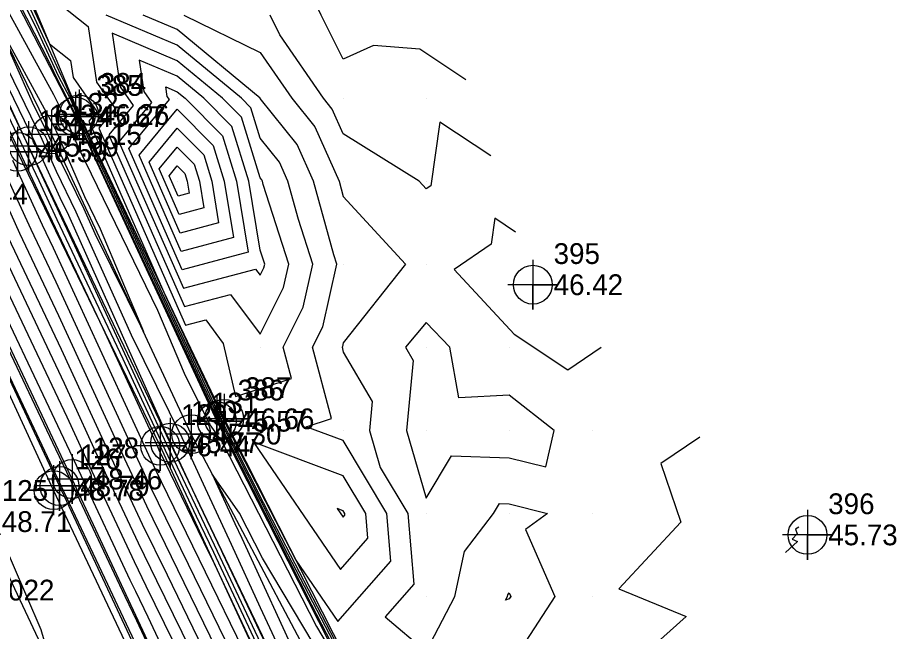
# Model space of a CAD drawing. Extents: x 2090860 to 2091277, y 159470 to 160080.
# Drawn here: x 2091170.8 to 2091276.6, y 159525.8 to 159599.7 of the extents above; entities that cross this region are included whole.
import ezdxf

# ---------------------------------------------------------------- set-up
doc = ezdxf.new("R2010")
doc.units = 0
for name, color, linetype in [('DTM Contours Major', 7, 'Continuous'), ('DTM Contours Minor', 7, 'Continuous'), ('Exist DTM Breakline', 7, 'Continuous'), ('Exist DTM Breakline Cogo Elevation', 7, 'Continuous'), ('Exist DTM Breakline Cogo Number', 7, 'Continuous'), ('Exist DTM Breakline Cogo Point CELL', 7, 'Continuous'), ('Exist DTM Crownline', 7, 'Continuous'), ('Exist DTM QL2 LIDAR Elevation Point', 7, 'Continuous'), ('Exist DTM Regular Point CELL', 7, 'Continuous'), ('Exist DTM Regular Point Cogo Elevation', 7, 'Continuous'), ('Exist DTM Regular Point Cogo Number', 7, 'Continuous'), ('Exist Roads EOP', 7, 'Continuous'), ('Exist Roads EOP Cogo Elevation', 7, 'Continuous'), ('Exist Roads EOP Cogo Number', 7, 'Continuous'), ('Exist Roads EOP Cogo Point CELL', 7, 'Continuous'), ('Exist Roads EOT', 7, 'Continuous'), ('Exist Roads EOT Cogo Comment', 7, 'Continuous'), ('Exist Roads EOT Cogo Elevation', 7, 'Continuous'), ('Exist Roads EOT Cogo Number', 7, 'Continuous'), ('Exist Roads EOT Cogo Point CELL', 7, 'Continuous')]:
    doc.layers.add(name, color=color, linetype=linetype)

msp = doc.modelspace()

# ---------------------------------------------------------------- linework, layer by layer
at = {"layer": 'DTM Contours Major'}
for points in [[(2091162.22, 159619.59), (2091172.87, 159598.82), (2091175.68, 159592.7), (2091177.05, 159590.04), (2091177.99, 159587.93), (2091182.7, 159577.85), (2091190.68, 159560.74), (2091193.18, 159555.38), (2091195.13, 159551.22), (2091203.3, 159535.13), (2091208.82, 159524.5), (2091210.51, 159521.16), (2091212.36, 159517.6), (2091212.6, 159516.12), (2091218.27, 159517.95), (2091225.53, 159506.04)], [(2091207.68, 159508.27), (2091198.7, 159527.23), (2091194.86, 159535.4), (2091190.69, 159544.21), (2091188.73, 159548.38), (2091177.66, 159572.24), (2091176.09, 159575.54), (2091172.14, 159584.12), (2091172.1, 159584.21), (2091171.96, 159584.5), (2091159.16, 159611.27)], [(2091227.76, 159583.05), (2091221.65, 159587.11), (2091220.56, 159579.46), (2091220, 159579.08), (2091219.16, 159580), (2091210, 159585.73), (2091208.68, 159588.68), (2091207.63, 159590), (2091202.35, 159597.65), (2091201.18, 159600)], [(2091200.18, 159580.18), (2091200, 159580.41), (2091197.73, 159587.73), (2091195.47, 159590), (2091190, 159594.52), (2091182.17, 159597.83), (2091183.14, 159591.36), (2091184.7, 159589.12), (2091181.77, 159585.59), (2091190.87, 159564.9), (2091196.43, 159566.38), (2091200, 159561.59), (2091202.8, 159567.2), (2091203.44, 159570), (2091200.37, 159579.63), (2091200.26, 159580), (2091200.18, 159580.18)], [(2091186.61, 159582.31), (2091190, 159586.4), (2091193.19, 159583.19), (2091194.18, 159580), (2091194.99, 159575.01), (2091190.36, 159573.77), (2091186.61, 159582.31)], [(2091204.41, 159506.84), (2091201.72, 159512.58), (2091191.37, 159533.84), (2091186.84, 159543.13), (2091185.01, 159547.03), (2091175.43, 159567.86), (2091172.41, 159574.21), (2091169.37, 159580.83)], [(2091199.12, 159504.14), (2091189.54, 159524.53), (2091186.27, 159531.24), (2091184.84, 159534.18), (2091179.74, 159545.05), (2091176.73, 159551.58), (2091166.95, 159572.18)], [(2091235.41, 159550), (2091230, 159554.23), (2091223.93, 159553.93), (2091222.82, 159560), (2091220, 159562.98), (2091217.49, 159560), (2091218.42, 159558.42), (2091217.63, 159550), (2091220, 159541.83), (2091223.05, 159546.95), (2091230, 159546.68), (2091234.41, 159545.59), (2091235.41, 159550)], [(2091252.96, 159549.2), (2091248.25, 159545.99), (2091250.64, 159538.93), (2091243.2, 159530.91), (2091251.29, 159527.59), (2091233.2, 159511.35)], [(2091210.19, 159540), (2091210, 159540.31), (2091209.25, 159540.59), (2091209.98, 159539.53), (2091210.21, 159539.79), (2091210.19, 159540)]]:
    msp.add_lwpolyline(points, dxfattribs=at)
at = {"layer": 'DTM Contours Minor'}
for points in [[(2091224.76, 159592.22), (2091219.22, 159595.9), (2091213.64, 159596.36), (2091210, 159594.69), (2091207.35, 159600), (2091204.79, 159605.21), (2091210, 159605.72), (2091210.64, 159610.83), (2091203.95, 159619.56), (2091203.03, 159627.79), (2091199.27, 159639.53), (2091192.99, 159662.41), (2091180.9, 159659.1), (2091180, 159656.91), (2091179.57, 159659.57), (2091178.38, 159660), (2091170, 159666.16)], [(2091219.63, 159519.56), (2091212.69, 159517.33), (2091212.63, 159517.73), (2091209.73, 159523.3), (2091209.08, 159524.59), (2091200.41, 159541.27), (2091195.33, 159551.28), (2091192.24, 159557.89), (2091190.87, 159560.84), (2091186.47, 159570.26), (2091178.17, 159588.03), (2091176.51, 159591.76), (2091176.02, 159592.72), (2091171.12, 159603.39), (2091162.73, 159619.75)], [(2091161.72, 159619.42), (2091174.62, 159594.26), (2091175.34, 159592.69), (2091177.59, 159588.32), (2091177.81, 159587.82), (2091178.92, 159585.45), (2091190.5, 159560.64), (2091194.12, 159552.87), (2091194.92, 159551.15), (2091206.18, 159528.99), (2091208.56, 159524.42), (2091211.29, 159519.03), (2091212.1, 159517.48), (2091212.51, 159514.92), (2091216.91, 159516.34), (2091222.54, 159507.09)], [(2091206.7, 159507.96), (2091205.1, 159511.33), (2091194.5, 159533.92), (2091193.91, 159535.13), (2091187.84, 159547.61), (2091187.65, 159548.02), (2091181.1, 159562.25), (2091174.97, 159575.16), (2091174.59, 159575.99), (2091170.96, 159583.65), (2091159.14, 159608.41)], [(2091208.17, 159508.43), (2091195.49, 159535.18), (2091195.33, 159535.53), (2091192.74, 159540.99), (2091189.37, 159548.23), (2091189.23, 159548.54), (2091188.88, 159549.24), (2091176.93, 159575.88), (2091175.9, 159577.99), (2091172.91, 159584.62), (2091161.2, 159608.69)], [(2091169.37, 159607.95), (2091174.6, 159596.57), (2091177.15, 159594.53), (2091177.46, 159592.48), (2091180.32, 159588.39), (2091179.36, 159587.24), (2091188.68, 159566.02), (2091190.25, 159562.66), (2091191.05, 159560.94), (2091191.3, 159560.4), (2091195.53, 159551.35), (2091197.53, 159547.41), (2091204.3, 159534.37), (2091209.35, 159526.97), (2091215.74, 159534.26), (2091215.24, 159540), (2091210, 159548.77), (2091205.55, 159550.43), (2091208.59, 159551.41), (2091206.3, 159560), (2091207.53, 159562.47), (2091209.23, 159570), (2091208.87, 159571.13), (2091206.41, 159580), (2091204.43, 159584.43), (2091200, 159589.98), (2091200, 159590), (2091199.99, 159590), (2091190, 159598.26), (2091185.89, 159600)], [(2091170.93, 159605.31), (2091179.29, 159598.64), (2091180.3, 159591.92), (2091182.51, 159588.76), (2091180.57, 159586.41), (2091190.99, 159562.68), (2091193.43, 159563.33), (2091195.55, 159560.48), (2091197.01, 159554.08), (2091203.75, 159556.25), (2091202.75, 159560), (2091205.17, 159564.83), (2091206.33, 159570), (2091204.62, 159575.38), (2091203.34, 159580), (2091202.31, 159582.31), (2091200, 159585.2), (2091198.86, 159588.86), (2091197.73, 159590), (2091190, 159596.39), (2091181.46, 159600)], [(2091168.28, 159602.91), (2091175.11, 159590.44), (2091176.8, 159587.07), (2091178.21, 159583.85), (2091187.64, 159564.48), (2091190.82, 159556.88), (2091193.94, 159550.68), (2091195.4, 159548.57), (2091206.77, 159526.37), (2091208.71, 159523.12), (2091211.92, 159516.82), (2091212.41, 159513.72), (2091215.54, 159514.73), (2091219.56, 159508.15)], [(2091190.81, 159600), (2091200, 159595.52), (2091203.81, 159590), (2091206.56, 159586.56), (2091209.49, 159580), (2091210, 159578.15), (2091217.5, 159570), (2091210, 159560.55), (2091209.9, 159560.1), (2091209.85, 159560), (2091210, 159559.43), (2091213.49, 159553.49), (2091213.16, 159550), (2091214.46, 159545.54), (2091217.77, 159540), (2091218.51, 159531.49), (2091215.05, 159527.53), (2091220, 159523.35), (2091223.42, 159530), (2091224.6, 159535.4), (2091228.1, 159540), (2091228.81, 159541.19), (2091230, 159541.14), (2091234.61, 159540), (2091231.96, 159538.04), (2091235.5, 159530), (2091230, 159521.53)], [(2091209.19, 159508.99), (2091200.05, 159528.61), (2091196.54, 159536.26), (2091193.16, 159543.51), (2091190.6, 159549.1), (2091184.5, 159561.46), (2091177.85, 159576.26), (2091175.47, 159581.17), (2091173.72, 159585.04), (2091166.89, 159599.08)], [(2091168.13, 159599.43), (2091174.94, 159587), (2091175.42, 159586.04), (2091178.85, 159578.16), (2091180.74, 159574.28), (2091185.93, 159561.89), (2091180.11, 159573.68), (2091178.78, 159576.64), (2091175.04, 159584.35), (2091174.54, 159585.46), (2091172.59, 159589.47), (2091168.13, 159599.43)], [(2091207.19, 159508.12), (2091201.9, 159519.28), (2091194.4, 159535.27), (2091192.33, 159539.63), (2091188.29, 159548.24), (2091183.5, 159558.57), (2091175.53, 159575.35), (2091173.36, 159580.06), (2091171.53, 159583.93), (2091165.55, 159596.46)], [(2091200.44, 159569.56), (2091200.54, 159570), (2091200, 159571.69), (2091198.64, 159580), (2091196.59, 159586.59), (2091193.21, 159590), (2091190, 159592.65), (2091185.41, 159594.59), (2091185.97, 159590.8), (2091186.89, 159589.48), (2091182.98, 159584.77), (2091190.74, 159567.12), (2091199.44, 159569.43), (2091200, 159568.68), (2091200.44, 159569.56)], [(2091189.08, 159589.85), (2091188.81, 159590.23), (2091188.64, 159591.36), (2091190, 159590.78), (2091190.95, 159590), (2091195.46, 159585.46), (2091197.15, 159580), (2091198.55, 159571.45), (2091190.61, 159569.34), (2091184.19, 159583.95), (2091189.08, 159589.85)], [(2091185.4, 159583.13), (2091190, 159588.68), (2091194.32, 159584.32), (2091195.66, 159580), (2091196.77, 159573.23), (2091190.49, 159571.56), (2091185.4, 159583.13)], [(2091187.82, 159581.48), (2091190, 159584.12), (2091192.05, 159582.05), (2091192.69, 159580), (2091193.21, 159576.79), (2091190.23, 159575.99), (2091187.82, 159581.48)], [(2091205.74, 159507.51), (2091204.76, 159509.59), (2091192.64, 159534.49), (2091187.34, 159545.37), (2091186.33, 159547.52), (2091175.11, 159571.93), (2091173.78, 159574.72), (2091170.21, 159582.49)], [(2091189.03, 159580.66), (2091190, 159581.84), (2091190.92, 159580.92), (2091191.2, 159580), (2091191.43, 159578.57), (2091190.1, 159578.21), (2091189.03, 159580.66)], [(2091203.09, 159506.17), (2091198.67, 159515.57), (2091190.09, 159533.19), (2091186.34, 159540.89), (2091183.69, 159546.53), (2091175.76, 159563.79), (2091171.05, 159573.7), (2091168.54, 159579.18)], [(2091230.76, 159573.88), (2091228.26, 159575.54), (2091227.81, 159572.42), (2091223.35, 159569.36), (2091230.59, 159561.58), (2091237.03, 159557.28), (2091241.07, 159560.04)], [(2091201.77, 159505.49), (2091195.63, 159518.56), (2091188.82, 159532.54), (2091185.84, 159538.66), (2091182.37, 159546.04), (2091176.08, 159559.72), (2091169.68, 159573.2)], [(2091200.45, 159504.82), (2091192.59, 159521.54), (2091187.55, 159531.89), (2091185.34, 159536.42), (2091181.06, 159545.54), (2091176.41, 159555.65), (2091168.32, 159572.69)], [(2091195.55, 159502.3), (2091196.44, 159502.8), (2091196.49, 159502.82), (2091185.13, 159527.04), (2091183.74, 159529.98), (2091177.96, 159542.28), (2091177.13, 159544.03), (2091175.38, 159547.74), (2091164.28, 159571.14)], [(2091197.8, 159503.47), (2091186.5, 159527.52), (2091185, 159530.6), (2091184.34, 159531.94), (2091178.42, 159544.55), (2091177.06, 159547.51), (2091165.59, 159571.67)], [(2091186.27, 159497.39), (2091194.8, 159502.18), (2091195.32, 159502.41), (2091193, 159507.34), (2091182.52, 159529.55), (2091181.63, 159531.44), (2091175.98, 159543.39), (2091164.06, 159568.64)], [(2091163.19, 159550.12), (2091173.59, 159526.02), (2091173.94, 159524.79), (2091174.26, 159523.65), (2091182.68, 159504.91), (2091186.18, 159497.42), (2091186.21, 159497.37)], [(2091212.72, 159540), (2091210, 159544.54), (2091199.2, 159548.58), (2091209.67, 159533.25), (2091212.97, 159537.03), (2091212.72, 159540)], [(2091216.57, 159509.2), (2091214.18, 159513.11), (2091212.32, 159512.51), (2091212.03, 159514.36), (2091210.11, 159518.11), (2091200.27, 159534.62), (2091197.5, 159540.02), (2091194.23, 159544.73), (2091196.95, 159538.79), (2091197.77, 159537.03), (2091204.97, 159521.37), (2091210.4, 159509.7)], [(2091264.86, 159538.36), (2091264.48, 159538.1), (2091264.67, 159537.53), (2091264.07, 159536.88), (2091264.72, 159536.61), (2091263.26, 159535.3)], [(2091229.82, 159530.18), (2091230, 159530.42), (2091230.19, 159530), (2091230, 159529.71), (2091229.54, 159529.54), (2091229.78, 159530), (2091229.82, 159530.18)]]:
    msp.add_lwpolyline(points, dxfattribs=at)
at = {"layer": 'Exist DTM Breakline'}
for points in [[(2091212.18, 159510.75), (2091191.69, 159549.55), (2091174.86, 159585.63), (2091158.43, 159619.3), (2091139.42, 159656.46), (2091124.85, 159687.37), (2091111.1, 159719.28), (2091102.68, 159740.8), (2091098.87, 159752.93), (2091092.87, 159757.67)], [(2091196.63, 159502.87), (2091177.33, 159544.14), (2091161.14, 159578.46), (2091145.39, 159612.39), (2091128.08, 159650.69), (2091112.84, 159682.38), (2091098.52, 159713.45), (2091088.42, 159738.26), (2091087.49, 159747.73)], [(2091104.06, 159746.7), (2091118.02, 159713.35), (2091131.54, 159686.37), (2091144.55, 159657.11), (2091164.61, 159620.38), (2091178.18, 159588.04), (2091195.66, 159551.39), (2091212.73, 159517.77)], [(2091103.08, 159746.11), (2091115.59, 159711.79), (2091128.14, 159684.6), (2091142.55, 159655.71), (2091161.44, 159619.32), (2091177.76, 159587.79), (2091194.78, 159551.1), (2091211.9, 159517.39)], [(2091206.49, 159507.9), (2091187.96, 159548.13), (2091170.75, 159583.55), (2091154.78, 159617.35), (2091136.61, 159654.77), (2091121.99, 159686.47), (2091108.44, 159717.46), (2091100.12, 159738.88)], [(2091208.29, 159508.47), (2091189.15, 159548.51), (2091172.11, 159584.22), (2091156.47, 159618.15), (2091137.83, 159655.46)]]:
    msp.add_lwpolyline(points, dxfattribs=at)
at = {"layer": 'Exist DTM Breakline Cogo Point CELL'}
for points in [[(2091177.76, 159590.79), (2091177.76, 159584.79), (2091177.76, 159587.79), (2091180.76, 159587.79), (2091174.76, 159587.79)], [(2091178.18, 159591.04), (2091178.18, 159585.04), (2091178.18, 159588.04), (2091181.18, 159588.04), (2091175.18, 159588.04)], [(2091174.86, 159588.63), (2091174.86, 159582.63), (2091174.86, 159585.63), (2091177.86, 159585.63), (2091171.86, 159585.63)], [(2091172.11, 159587.22), (2091172.11, 159581.22), (2091172.11, 159584.22), (2091175.11, 159584.22), (2091169.11, 159584.22)], [(2091170.75, 159586.55), (2091170.75, 159580.55), (2091170.75, 159583.55), (2091173.75, 159583.55), (2091167.75, 159583.55)], [(2091194.78, 159554.1), (2091194.78, 159548.1), (2091194.78, 159551.1), (2091197.78, 159551.1), (2091191.78, 159551.1)], [(2091195.66, 159554.39), (2091195.66, 159548.39), (2091195.66, 159551.39), (2091198.66, 159551.39), (2091192.66, 159551.39)], [(2091191.69, 159552.55), (2091191.69, 159546.55), (2091191.69, 159549.55), (2091194.69, 159549.55), (2091188.69, 159549.55)], [(2091187.96, 159551.13), (2091187.96, 159545.13), (2091187.96, 159548.13), (2091190.96, 159548.13), (2091184.96, 159548.13)], [(2091189.15, 159551.51), (2091189.15, 159545.51), (2091189.15, 159548.51), (2091192.15, 159548.51), (2091186.15, 159548.51)], [(2091177.33, 159547.14), (2091177.33, 159541.14), (2091177.33, 159544.14), (2091180.33, 159544.14), (2091174.33, 159544.14)]]:
    msp.add_lwpolyline(points, dxfattribs=at)
for centre in [(2091177.76, 159587.79), (2091178.18, 159588.04), (2091174.86, 159585.63), (2091170.75, 159583.55), (2091172.11, 159584.22), (2091194.78, 159551.1), (2091195.66, 159551.39), (2091191.69, 159549.55), (2091187.96, 159548.13), (2091189.15, 159548.51), (2091177.33, 159544.14)]:
    msp.add_circle(centre, 2.34, dxfattribs=at)
at = {"layer": 'Exist DTM Crownline'}
msp.add_lwpolyline([(2091186.23, 159497.37), (2091150.27, 159573.79), (2091135.08, 159606.79), (2091117.27, 159645.44), (2091102.61, 159676.95), (2091088.1, 159708.38), (2091072.92, 159741.27)], dxfattribs=at)
at = {"layer": 'Exist DTM QL2 LIDAR Elevation Point'}
for p, q in [((2091190, 159590), (2091190, 159590)), ((2091200, 159590), (2091200, 159590)), ((2091210, 159590), (2091210, 159590)), ((2091220, 159590), (2091220, 159590)), ((2091190, 159580), (2091190, 159580)), ((2091200, 159580), (2091200, 159580)), ((2091210, 159580), (2091210, 159580)), ((2091220, 159580), (2091220, 159580)), ((2091200, 159570), (2091200, 159570)), ((2091210, 159570), (2091210, 159570)), ((2091220, 159570), (2091220, 159570)), ((2091200, 159560), (2091200, 159560)), ((2091210, 159560), (2091210, 159560)), ((2091220, 159560), (2091220, 159560)), ((2091230, 159560), (2091230, 159560)), ((2091210, 159550), (2091210, 159550)), ((2091220, 159550), (2091220, 159550)), ((2091230, 159550), (2091230, 159550)), ((2091240, 159550), (2091240, 159550)), ((2091210, 159540), (2091210, 159540)), ((2091220, 159540), (2091220, 159540)), ((2091230, 159540), (2091230, 159540)), ((2091240, 159540), (2091240, 159540)), ((2091220, 159530), (2091220, 159530)), ((2091230, 159530), (2091230, 159530)), ((2091240, 159530), (2091240, 159530))]:
    msp.add_line(p, q, dxfattribs=at)
at = {"layer": 'Exist DTM Regular Point CELL'}
for points in [[(2091232.84, 159570.54), (2091232.84, 159564.54), (2091232.84, 159567.54), (2091235.84, 159567.54), (2091229.84, 159567.54)], [(2091265.91, 159540.41), (2091265.91, 159534.41), (2091265.91, 159537.41), (2091268.91, 159537.41), (2091262.91, 159537.41)]]:
    msp.add_lwpolyline(points, dxfattribs=at)
for centre in [(2091232.84, 159567.54), (2091265.91, 159537.41)]:
    msp.add_circle(centre, 2.34, dxfattribs=at)
at = {"layer": 'Exist Roads EOP'}
msp.add_lwpolyline([(2091195.02, 159502.3), (2091175.82, 159543.3), (2091159.6, 159577.85), (2091143.94, 159611.54), (2091126.2, 159649.8), (2091111.24, 159681.73), (2091096.72, 159712.78), (2091082.12, 159745.37)], dxfattribs=at)
at = {"layer": 'Exist Roads EOP Cogo Point CELL'}
msp.add_lwpolyline([(2091175.82, 159546.3), (2091175.82, 159540.3), (2091175.82, 159543.3), (2091178.82, 159543.3), (2091172.82, 159543.3)], dxfattribs=at)
msp.add_circle((2091175.82, 159543.3), 2.34, dxfattribs=at)
at = {"layer": 'Exist Roads EOT'}
msp.add_lwpolyline([(2091194.37, 159502.02), (2091175.12, 159542.8), (2091158.99, 159577.7), (2091143.37, 159611.22), (2091125.35, 159649.38), (2091110.43, 159681.3), (2091096.01, 159712.51), (2091081.14, 159744.98)], dxfattribs=at)
at = {"layer": 'Exist Roads EOT Cogo Point CELL'}
msp.add_lwpolyline([(2091175.12, 159545.8), (2091175.12, 159539.8), (2091175.12, 159542.8), (2091172.12, 159542.8), (2091178.12, 159542.8)], dxfattribs=at)
msp.add_circle((2091175.12, 159542.8), 2.34, dxfattribs=at)

# ---------------------------------------------------------------- texts
at = {"layer": 'Exist DTM Breakline Cogo Elevation'}
for s, p in [('45.67', (2091180.26, 159586.54)), ('46.26', (2091180.68, 159586.79)), ('45.15', (2091177.36, 159584.38)), ('46.59', (2091173.25, 159582.3)), ('45.99', (2091174.61, 159582.97)), ('48.44', (2091163.64, 159577.21)), ('45.57', (2091197.28, 159549.85)), ('46.66', (2091198.16, 159550.14)), ('45.30', (2091194.19, 159548.3)), ('46.44', (2091190.46, 159546.88)), ('45.77', (2091191.65, 159547.26)), ('48.46', (2091179.83, 159542.89))]:
    msp.add_text(s, height=2.5, dxfattribs=at).set_placement(p)
at = {"layer": 'Exist DTM Breakline Cogo Number'}
for s, p in [('385', (2091180.26, 159590.29)), ('384', (2091180.68, 159590.54)), ('132', (2091177.36, 159588.13)), ('133', (2091174.61, 159586.72)), ('134', (2091173.25, 159586.05)), ('387', (2091198.16, 159553.89)), ('386', (2091197.28, 159553.6)), ('131', (2091194.19, 159552.05)), ('129', (2091190.46, 159550.63)), ('130', (2091191.65, 159551.01)), ('128', (2091179.83, 159546.64))]:
    msp.add_text(s, height=2.5, dxfattribs=at).set_placement(p)
at = {"layer": 'Exist DTM Regular Point Cogo Elevation'}
for s, p in [('46.42', (2091235.34, 159566.29)), ('45.73', (2091268.41, 159536.16))]:
    msp.add_text(s, height=2.5, dxfattribs=at).set_placement(p)
at = {"layer": 'Exist DTM Regular Point Cogo Number'}
for s, p in [('395', (2091235.34, 159570.04)), ('396', (2091268.41, 159539.91))]:
    msp.add_text(s, height=2.5, dxfattribs=at).set_placement(p)
at = {"layer": 'Exist Roads EOP Cogo Elevation'}
msp.add_text('48.79', height=2.5, dxfattribs=at).set_placement((2091178.32, 159542.05))
at = {"layer": 'Exist Roads EOP Cogo Number'}
msp.add_text('127', height=2.5, dxfattribs=at).set_placement((2091178.32, 159545.8))
at = {"layer": 'Exist Roads EOT Cogo Comment'}
msp.add_text('*BL30022', height=2.5, dxfattribs=at).set_placement((2091160.53, 159529.51))
at = {"layer": 'Exist Roads EOT Cogo Elevation'}
for s, p in [('48.78', (2091177.62, 159541.55)), ('48.71', (2091168.87, 159537.76))]:
    msp.add_text(s, height=2.5, dxfattribs=at).set_placement(p)
at = {"layer": 'Exist Roads EOT Cogo Number'}
for s, p in [('126', (2091177.62, 159545.3)), ('125', (2091168.87, 159541.51))]:
    msp.add_text(s, height=2.5, dxfattribs=at).set_placement(p)

doc.saveas('drawing.dxf')
